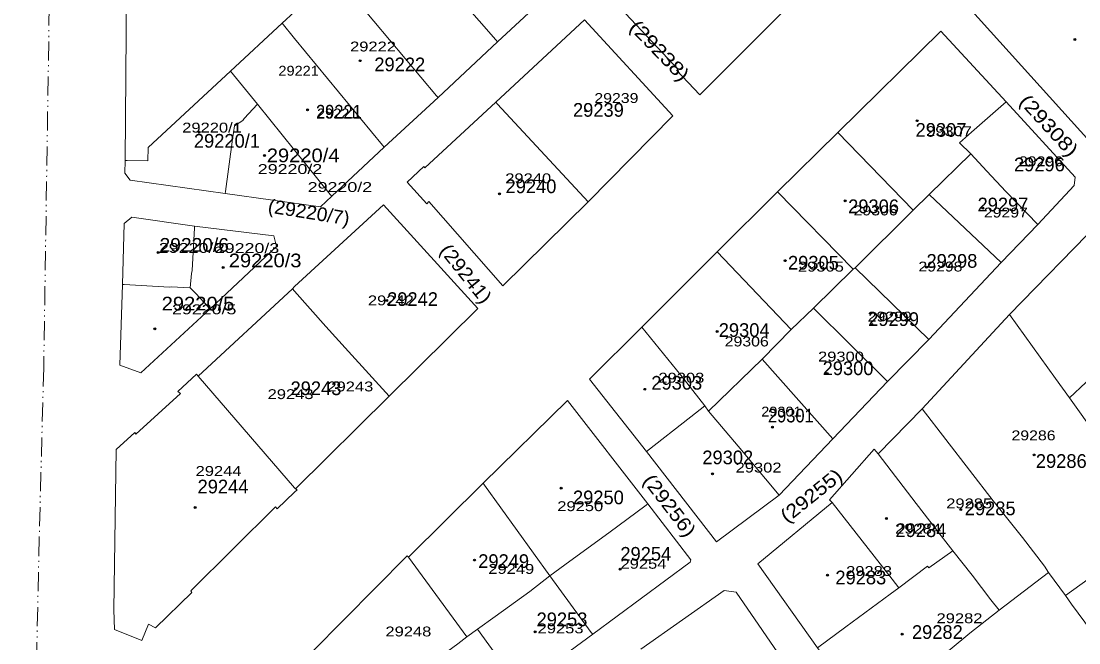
# Model space of a CAD drawing. Extents: x 650553 to 652508, y 239277 to 241647.
# Drawn here: x 650553 to 650831.5, y 239562.7 to 239726.3 of the extents above; entities that cross this region are included whole.
import ezdxf

# ---------------------------------------------------------------- set-up
doc = ezdxf.new("R2010")
doc.units = 0
doc.header["$PDMODE"] = 32
doc.header["$PDSIZE"] = 0.5
doc.linetypes.add('DASH_DOUBLE_DOT', pattern=[9.2, 5, -1.2, 0.3, -1.2, 0.3, -1.2])
for name, color, linetype in [('19', 7, 'Continuous'), ('20', 7, 'Continuous'), ('6', 7, 'Continuous')]:
    doc.layers.add(name, color=color, linetype=linetype)
for name, color, linetype, lineweight in [('3', 7, 'Continuous', 13), ('5', 7, 'Continuous', 13), ('52', 7, 'DASH_DOUBLE_DOT', 13)]:
    doc.layers.add(name, color=color, linetype=linetype, lineweight=lineweight)

msp = doc.modelspace()

# ---------------------------------------------------------------- linework, layer by layer
at = {"layer": '3'}
for p, q in [((650724.616, 239701.337), (650702.33, 239678.75)), ((650631.87, 239677.45), (650606.76, 239680.97)), ((650702.33, 239678.75), (650679.85, 239656.67)), ((650696.87, 239626.46), (650718.04, 239599.25)), ((650654.66, 239585.53), (650654.96, 239585.23))]:
    msp.add_line(p, q, dxfattribs=at)
for points in [[(650580.38, 239689.62), (650580.75, 239734.46), (650612.1, 239763.93), (650627.06, 239777.69), (650640.68, 239790.82), (650654.82, 239804.68), (650668.76, 239818.06), (650682.12, 239830.96), (650716.35, 239864.08), (650745.15, 239891.65)], [(650768.36, 239864.8), (650794.405, 239833.862), (650796.608, 239830.924), (650793.863, 239828.628), (650782.78, 239817.68), (650768.67, 239804.67), (650748.15, 239785.39), (650733.99, 239772.3), (650719.95, 239759.65), (650706.09, 239746.56), (650692.5, 239733.96), (650678.47, 239720.85), (650662.83, 239706.18), (650648.6, 239693.12), (650634.81, 239680.2), (650631.87, 239677.45)], [(650760.22, 239736.65), (650760.87, 239736.09), (650731.71, 239706.88), (650725.59, 239713.35), (650725.99, 239713.6), (650708.05, 239732.82), (650737.88, 239760.92), (650754.83, 239776.64), (650770.26, 239790.78), (650780.2, 239800.09), (650804.13, 239822.14)], [(650858.42, 239712.84), (650837.68, 239691.06), (650802.53, 239729.93)], [(650679.85, 239656.67), (650660.338, 239678.861), (650659.846, 239678.207), (650654.69, 239683.89), (650659.02, 239688.01), (650659.31, 239687.67), (650677.97, 239704.96), (650701.302, 239726.619), (650724.616, 239701.337)], [(650606.76, 239680.97), (650581.73, 239684.41), (650580.31, 239686.26), (650580.38, 239689.62)], [(650625, 239656.48), (650648.46, 239677.93), (650673.22, 239650.68), (650649.94, 239627.6), (650625.24, 239603.19), (650625.65, 239602.9), (650625, 239602.29)], [(650580.16, 239673.01), (650582.19, 239674.72), (650598.69, 239672.37)], [(650766.66, 239555.85), (650762.69, 239561.36), (650746.99, 239583.49), (650766.57, 239599.63), (650765.87, 239600.32), (650777.65, 239613.61), (650778.65, 239612.38), (650790.25, 239624.22), (650813.28, 239649.12), (650837.06, 239673.5), (650840.71, 239673.57), (650857.5, 239654.04), (650866.83, 239643.35), (650876.22, 239632.41), (650885.67, 239621.34), (650903.75, 239600.18), (650931.7, 239568.01), (650902.59, 239545.65), (650893.39, 239538.45), (650868.88, 239519.76), (650843.34, 239500)], [(650602.74, 239650.57), (650584.5, 239633.7), (650579.02, 239635.78), (650579.669, 239656.979), (650580.16, 239673.01)], [(650598.69, 239672.37), (650619.53, 239669.83), (650620.2, 239667.01), (650602.74, 239650.57)], [(650625, 239656.48), (650624.45, 239655.88), (650599.63, 239632.85), (650599.21, 239633.38), (650594.27, 239628.84), (650594.94, 239628.28), (650583.18, 239617.58), (650582.92, 239618.03), (650578.04, 239613.55), (650577.43, 239571.39), (650577.57, 239566.21), (650584.77, 239563.25), (650586.52, 239567.59), (650588.36, 239566.63), (650597.96, 239575.96), (650597.7, 239576.38), (650620, 239598.43), (650620.42, 239597.93), (650625, 239602.29)], [(650654.96, 239585.23), (650674.63, 239604.67), (650696.87, 239626.46)], [(650718.04, 239599.25), (650729.3, 239584.51), (650729.19, 239583.87), (650703.5, 239564.91), (650684.32, 239550.84), (650665.13, 239536.9), (650641.42, 239520.61), (650610.36, 239500)], [(650574.582, 239477.239), (650574.134, 239480.709), (650574.717, 239503.811), (650574.49, 239505.368), (650574.913, 239506.43), (650575.36, 239507.491), (650576.588, 239508.285), (650595.268, 239525.716), (650621.254, 239551.909), (650654.66, 239585.53)], [(650716.19, 239560.97), (650738.16, 239576.42), (650741.28, 239575.98), (650755.11, 239555.85), (650767.89, 239537.86), (650780.51, 239519.85), (650811.5, 239476.07)]]:
    msp.add_lwpolyline(points, dxfattribs=at)
msp.add_lwpolyline([(650795.21, 239723.65), (650812.33, 239705.04), (650830.57, 239685.23), (650830.31, 239683.08), (650820.72, 239672.73), (650811.07, 239662.75), (650792.02, 239642.48), (650781.17, 239631.48), (650766.74, 239616.33), (650752.6, 239601.5), (650736.07, 239589.29), (650717.68, 239613.05), (650702.64, 239632.07), (650716.44, 239645.74), (650736.24, 239665.56), (650752.2, 239681.34), (650768.08, 239697)], close=True, dxfattribs=at)
at = {"layer": '5'}
for p, q in [((650621.7, 239725.75), (650625, 239721.74)), ((650615.22, 239704.45), (650625, 239692.34)), ((650787.92, 239676.53), (650768.08, 239697)), ((650772.1, 239661.02), (650752.2, 239681.34)), ((650792.09, 239680.65), (650811.07, 239662.75)), ((650755.77, 239645.17), (650736.24, 239665.56)), ((650772.64, 239661.37), (650792.02, 239642.48)), ((650597.54, 239656.07), (650598.99, 239654.62)), ((650624.45, 239655.88), (650625, 239655.25)), ((650857.5, 239654.04), (650829.08, 239627.18)), ((650761.65, 239650.78), (650781.17, 239631.48)), ((650748.1, 239637.32), (650766.74, 239616.33)), ((650599.63, 239632.85), (650625, 239603.48)), ((650625, 239603.48), (650625.24, 239603.19)), ((650654.96, 239585.23), (650670.35, 239564.25))]:
    msp.add_line(p, q, dxfattribs=at)
for points in [[(650637.65, 239736.16), (650662.41, 239706.68), (650662.83, 239706.18)], [(650664.79, 239736.5), (650678.033, 239721.35), (650678.47, 239720.85)], [(650580.38, 239689.62), (650580.88, 239689.614), (650586.4, 239689.55), (650586.41, 239693.04), (650608.13, 239713.16), (650621.7, 239725.75), (650625, 239728.79)], [(650625, 239721.74), (650648.188, 239693.62), (650648.6, 239693.12)], [(650606.76, 239680.97), (650606.827, 239681.47), (650608.57, 239694.55), (650608.66, 239695.2), (650609.17, 239698.74), (650611.38, 239700.11), (650611.71, 239700.63), (650615.22, 239704.45), (650608.13, 239713.16)], [(650677.97, 239704.96), (650678.435, 239704.46), (650702.33, 239678.75)], [(650812.33, 239705.04), (650803.22, 239697.11), (650800.09, 239694.27), (650803.05, 239691.36), (650792.09, 239680.65), (650787.92, 239676.53), (650772.64, 239661.37), (650772.1, 239661.02), (650761.65, 239650.78), (650755.77, 239645.17), (650748.1, 239637.32), (650734.01, 239623.67), (650733.01, 239625.07), (650729.37, 239622.15), (650717.68, 239613.05)], [(650625, 239692.34), (650634.406, 239680.7), (650634.81, 239680.2)], [(650803.05, 239691.36), (650807.31, 239686.82), (650812.28, 239681.44), (650820.72, 239672.73)], [(650598.69, 239672.37), (650598.661, 239671.87), (650598.02, 239660.71), (650597.89, 239659.9), (650597.54, 239656.07), (650592.51, 239656.4), (650592.03, 239656.28)], [(650592.03, 239656.28), (650580.169, 239656.951), (650579.669, 239656.979)], [(650598.99, 239654.62), (650602.277, 239651.07), (650602.74, 239650.57)], [(650625, 239655.25), (650633.25, 239645.89), (650639.24, 239639.32), (650649.94, 239627.6)], [(650813.28, 239649.12), (650825.35, 239632.21), (650829.08, 239627.18), (650836.27, 239617.04), (650844.45, 239605.56), (650852.96, 239593.81), (650855.66, 239590.17), (650893.39, 239538.45)], [(650716.44, 239645.74), (650726.69, 239633.14), (650733.01, 239625.07)], [(650734.01, 239623.67), (650741.81, 239614.42), (650752.6, 239601.5)], [(650790.25, 239624.22), (650808.99, 239600.06), (650816.68, 239590.35), (650822.43, 239582.83), (650823.49, 239581.14), (650828, 239575.1), (650829.56, 239572.82), (650868.88, 239519.76)], [(650885.67, 239621.34), (650861.68, 239601.04), (650856.01, 239596.37), (650854.86, 239595.27), (650852.96, 239593.81), (650847.23, 239589.49), (650833.94, 239579.39), (650828, 239575.1)], [(650778.65, 239612.38), (650788.67, 239599.38), (650795.28, 239590.84), (650798.36, 239586.91), (650803.38, 239580.49), (650808.32, 239573.96), (650810.56, 239571.23), (650823.49, 239581.14)], [(650674.63, 239604.67), (650674.991, 239604.17), (650692.22, 239580.3)], [(650718.04, 239599.25), (650717.54, 239598.88), (650707.71, 239591.61), (650697.46, 239584.18), (650692.22, 239580.3), (650686.94, 239576.22), (650677.82, 239569.6), (650673.19, 239566.23), (650670.35, 239564.25), (650667.97, 239562.39), (650658.79, 239555.61), (650654.51, 239552.4), (650648.09, 239548.02), (650641.32, 239543.45), (650631.74, 239536.94), (650630.85, 239536.19)], [(650766.57, 239599.63), (650782.34, 239579.46), (650784.15, 239577.16), (650781.87, 239575.48), (650770.15, 239566.89), (650762.69, 239561.36)], [(650784.15, 239577.16), (650791.64, 239582.88), (650792.04, 239582.4), (650798.36, 239586.91)], [(650692.22, 239580.3), (650703.134, 239565.41), (650703.5, 239564.91)], [(650810.56, 239571.23), (650802.8, 239565.19), (650797.62, 239560.92), (650797.03, 239560.44), (650798.19, 239558.67), (650799.89, 239556.69), (650814.88, 239535.76)], [(650673.19, 239566.23), (650683.958, 239551.34), (650684.32, 239550.84)]]:
    msp.add_lwpolyline(points, dxfattribs=at)
at = {"layer": '52'}
msp.add_lwpolyline([(650605.404, 240765.589), (650575.102, 240622.376), (650564.111, 240019.547), (650563.292, 239912.239), (650561.967, 239831.306), (650558.948, 239635.138), (650557.76, 239590.469), (650555.824, 239499.761), (650555.114, 239481.758), (650553.994, 239393.396), (650554.019, 239393.395), (650553.222, 239318.763), (650553.006, 239301.006), (650586.911, 239277.281)], dxfattribs=at)
at = {"layer": '6'}
for p in [(650830.497, 239721.44), (650642.253, 239715.885), (650628.442, 239702.975), (650701.73, 239702.684), (650788.935, 239700.09), (650599.842, 239697.065), (650617.107, 239690.95), (650816.289, 239688.885), (650678.945, 239680.815), (650769.999, 239679.01), (650806.215, 239677.055), (650589.108, 239665.395), (650754.179, 239663.255), (650606.19, 239661.47), (650791.396, 239661.565), (650649.258, 239652.765), (650588.198, 239645.339), (650777.014, 239646.425), (650736.291, 239644.615), (650765.257, 239633.555), (650625.333, 239629.535), (650717.189, 239629.395), (650750.804, 239619.41), (650819.713, 239612.11), (650735.04, 239607.18), (650695.194, 239603.38), (650598.852, 239598.315), (650780.826, 239595.385), (650800.395, 239597.725), (650672.371, 239584.46), (650710.694, 239582.08), (650765.323, 239580.495), (650688.342, 239565.57), (650784.995, 239564.93)]:
    msp.add_point(p, dxfattribs=at)

# ---------------------------------------------------------------- texts
at = {"layer": '19'}
for s, rotation, width, p in [('(29238)', 314.047, 1.2, (650712.887, 239724.44)), ('(29308)', 312.51, 1.2, (650815.559, 239704.961)), ('(29220/7)', 350.864, 1.05, (650617.814, 239675.964)), ('(29241)', 308.732, 1.1, (650663.003, 239665.82)), ('(29256)', 307.453, 1.15, (650716.52, 239605.305)), ('(29255)', 38.834, 1.15, (650754.727, 239594.041))]:
    msp.add_text(s, height=3.6, rotation=rotation, dxfattribs=dict(at, width=width)).set_placement(p)
for s, p in [('29222', (650646.005, 239713.107)), ('29239', (650698.313, 239701.135)), ('29307', (650788.521, 239695.868)), ('29220/1', (650598.489, 239692.994)), ('29296', (650814.432, 239686.77)), ('29240', (650680.556, 239681.023)), ('29306', (650770.766, 239675.756)), ('29297', (650804.835, 239676.235)), ('29298', (650791.398, 239661.39)), ('29305', (650754.929, 239660.911)), ('29242', (650649.366, 239651.334)), ('29299', (650776.042, 239646.067)), ('29304', (650736.693, 239643.193)), ('29300', (650764.046, 239633.137)), ('29243', (650623.933, 239627.87)), ('29303', (650718.939, 239629.306)), ('29302', (650732.375, 239609.673)), ('29286', (650820.191, 239608.716)), ('29244', (650599.458, 239602.011)), ('29250', (650698.313, 239599.138)), ('29285', (650801.476, 239596.265)), ('29284', (650783.24, 239590.519)), ('29254', (650710.79, 239584.294)), ('29249', (650673.361, 239582.378)), ('29283', (650767.405, 239578.068)), ('29253', (650688.717, 239567.055)), ('29282', (650787.559, 239563.703))]:
    msp.add_text(s, height=3.6, dxfattribs=at).set_placement(p)
for s, width, p in [('29221', 0.9, (650630.649, 239700.657)), ('29220/4', 1.1, (650617.684, 239689.163)), ('29220/6', 1.05, (650589.443, 239665.613)), ('29220/3', 1.1, (650607.677, 239661.514)), ('29220/5', 1.1, (650590.009, 239650.143)), ('29301', 0.9, (650749.65, 239620.687))]:
    msp.add_text(s, height=3.6, dxfattribs=dict(at, width=width)).set_placement(p)
at = {"layer": '20'}
for s, width, p in [('29222', 1.25, (650639.612, 239718.316)), ('29221', 1.1, (650620.749, 239711.934)), ('29239', 1.2, (650703.944, 239704.75)), ('29221', 1.1, (650630.911, 239700.686)), ('29220/1', 1.25, (650595.41, 239696.972)), ('29307', 1.25, (650791.288, 239696.042)), ('29296', 1.2, (650815.741, 239688.112)), ('29220/2', 1.35, (650615.314, 239686.063)), ('29240', 1.25, (650680.475, 239683.627)), ('29220/2', 1.35, (650628.46, 239681.331)), ('29306', 1.2, (650772.198, 239675.171)), ('29297', 1.2, (650806.491, 239674.618)), ('29220/6', 1.35, (650589.253, 239665.311)), ('29220/3', 1.35, (650604.003, 239665.265)), ('29305', 1.25, (650757.561, 239660.381)), ('29298', 1.2, (650789.262, 239660.405)), ('29242', 1.25, (650644.311, 239651.499)), ('29220/5', 1.35, (650592.724, 239649.146)), ('29299', 1.2, (650775.903, 239647.239)), ('29306', 1.2, (650738.258, 239640.68)), ('29300', 1.25, (650762.833, 239636.714)), ('29243', 1.25, (650633.645, 239628.843)), ('29303', 1.25, (650720.81, 239631.144)), ('29243', 1.25, (650617.903, 239626.823)), ('29301', 1.1, (650747.88, 239622.23)), ('29286', 1.2, (650813.777, 239615.967)), ('29244', 1.25, (650598.945, 239606.596)), ('29302', 1.25, (650741.138, 239607.501)), ('29250', 1.25, (650694.177, 239597.334)), ('29285', 1.25, (650796.591, 239598.062)), ('29284', 1.25, (650783.139, 239591.408)), ('29254', 1.25, (650710.825, 239582.173)), ('29249', 1.25, (650676.009, 239580.819)), ('29283', 1.25, (650770.233, 239580.265)), ('29282', 1.25, (650794.041, 239567.844)), ('29253', 1.25, (650688.997, 239565.171)), ('29248', 1.25, (650648.928, 239564.357))]:
    msp.add_text(s, height=2.6, dxfattribs=dict(at, width=width)).set_placement(p)

doc.saveas('drawing.dxf')
